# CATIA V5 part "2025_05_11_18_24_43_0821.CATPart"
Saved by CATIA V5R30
Part number: 2025_05_11_18_24_43_0821
Definition: 2025_05_11_18_24_43_0821
Nomenclature: 2025_05_11_18_24_43_0821
Source: Unknown
Description: PART-2025_05_11_18_24_43_0821-DESC
Bounding box of the stored display mesh (mm): x 240.75 to 266.25, y -12.75 to 12.75, z 0 to 53
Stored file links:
  E:\Bakalarka\Model\Forma_v7\2025_05_11_18_24_43_0821.CATPart
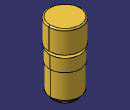
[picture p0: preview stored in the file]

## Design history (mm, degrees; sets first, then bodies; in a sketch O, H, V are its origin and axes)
Body1 "MANIFOLD_SOLID_BREP #148" (main body)
  Solid1: solid without history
